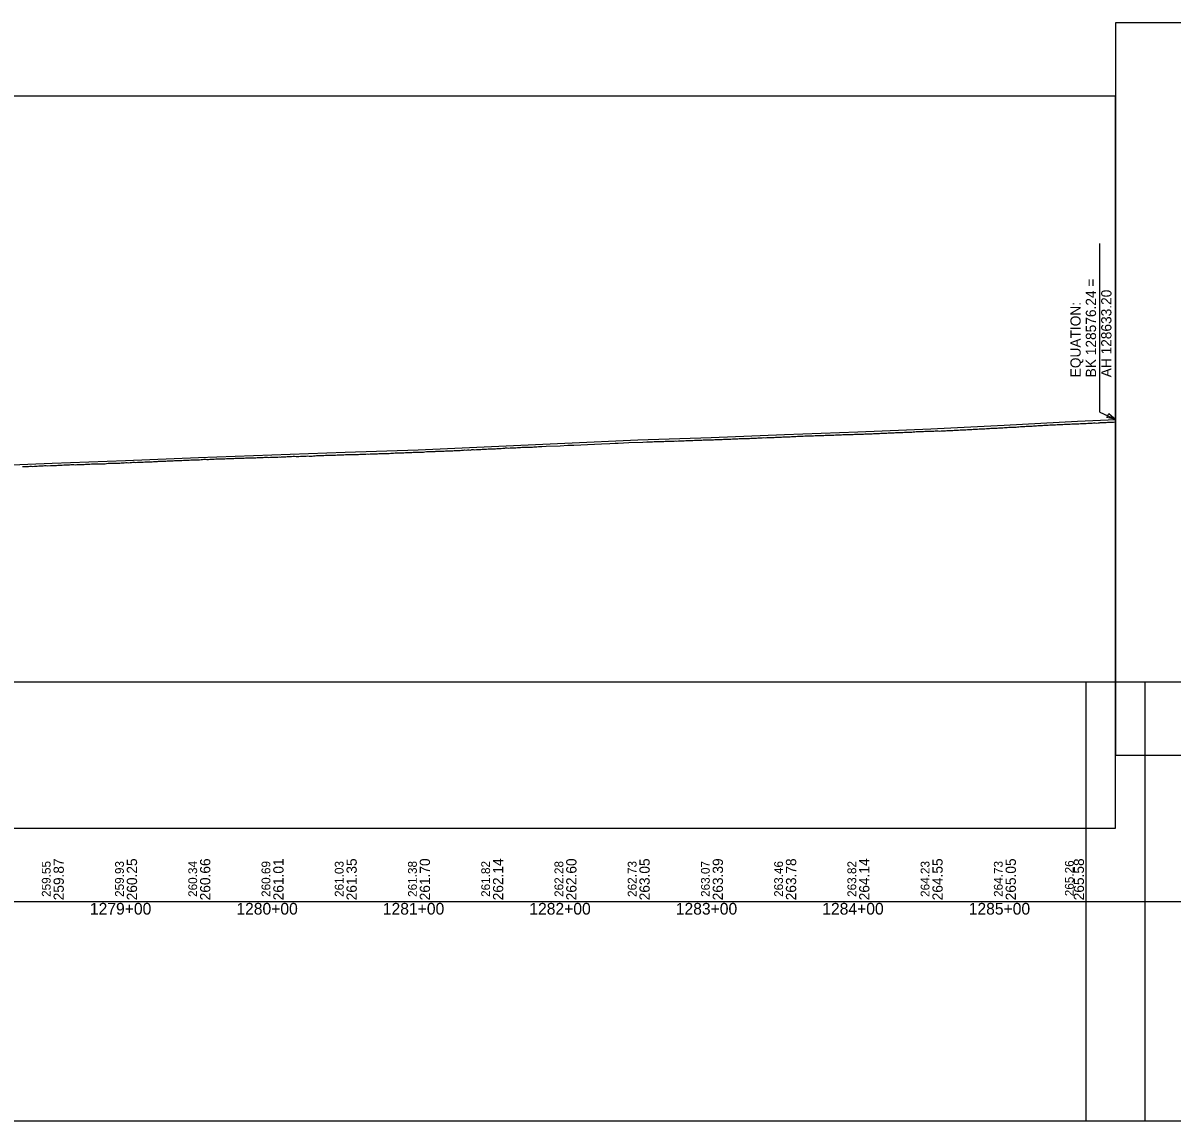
# Model space of a CAD drawing. Extents: x -3627 to 47473, y 2850 to 4350.
# Drawn here: x 15207 to 15992, y 2850 to 3600 of the extents above; entities that cross this region are included whole.
import ezdxf

# ---------------------------------------------------------------- set-up
doc = ezdxf.new("R2010")
doc.units = 0
for name, color, linetype in [('RD_DDB_Profile_EX', 7, 'Continuous'), ('RD_DDB_Profile_PR', 7, 'Continuous'), ('RD_DDB_StaTX', 7, 'Continuous'), ('RD_DDB_StripGrade', 7, 'Continuous'), ('RD_DDB_VCLbl', 7, 'Continuous'), ('RD_GPK_Profile_Cell', 7, 'Continuous'), ('RD_SHT_ShtClip', 7, 'Continuous')]:
    doc.layers.add(name, color=color, linetype=linetype)

msp = doc.modelspace()

# ---------------------------------------------------------------- linework, layer by layer
at = {"layer": 'RD_DDB_Profile_EX'}
for points in [[(15881.451196, 3323.85646), (15882.423116, 3323.95), (15883.423463, 3323.95), (15884.418069, 3323.956615), (15885.424679, 3324.013165), (15886.419282, 3324.15), (15887.41962, 3324.25), (15888.42183, 3324.3), (15889.420835, 3324.343355), (15890.4222, 3324.44327), (15891.424419, 3324.45), (15892.417994, 3324.5068), (15893.424781, 3324.556795), (15894.419207, 3324.6), (15895.420583, 3324.7), (15896.426294, 3324.6637), (15897.421796, 3324.83631), (15898.422092, 3324.89308), (15899.423454, 3324.92802), (15900.424384, 3324.97764), (15901.424671, 3325.07095), (15902.419335, 3325.156995), (15903.420494, 3325.15705), (15904.427249, 3325.228855), (15905.420825, 3325.321815), (15906.423081, 3325.314235), (15907.417768, 3325.364255), (15908.423403, 3325.46422), (15909.425667, 3325.564365), (15910.419243, 3325.60718), (15911.420616, 3325.607265), (15912.427126, 3325.614465), (15913.421829, 3325.657245), (15914.422061, 3325.792685), (15915.417694, 3325.80731), (15916.424416, 3325.76462), (15917.424638, 3325.85), (15918.420289, 3325.864755), (15919.420509, 3325.9149), (15920.420578, 3325.95737), (15921.421723, 3326.00743), (15922.423094, 3326.06503), (15923.416669, 3326.115025), (15924.424308, 3326.15), (15925.425678, 3326.15), (15926.419254, 3326.28485), (15927.421583, 3326.311775), (15928.420468, 3326.257555), (15929.421839, 3326.34236), (15930.422974, 3326.384605), (15931.423053, 3326.43476), (15932.423224, 3326.49231), (15933.425557, 3326.5), (15934.420343, 3326.55), (15935.425799, 3326.642245), (15936.421555, 3326.6345), (15937.421715, 3326.6), (15938.423083, 3326.792095), (15939.42293, 3326.7922), (15940.424298, 3326.757885), (15941.417873, 3326.876345), (15942.434896, 3326.94205), (15942.956564, 3327.015865), (15943.963958, 3327.05), (15944.965018, 3327.1), (15945.959348, 3327.06593), (15946.965961, 3327.157965), (15947.960289, 3327.292055), (15948.961338, 3327.308015), (15949.957103, 3327.35801), (15950.962282, 3327.392005), (15951.965544, 3327.44194), (15952.95909, 3327.5), (15953.566013, 3327.535008)], [(15681.807675, 3315.538865), (15682.808492, 3315.5723), (15683.807862, 3315.54427), (15684.807231, 3315.57197), (15685.808635, 3315.65), (15687.029535, 3315.71094), (15687.806753, 3315.721655), (15688.801588, 3315.77162), (15689.807375, 3315.82156), (15690.802205, 3315.771525), (15691.801493, 3315.882015), (15692.808516, 3315.95), (15693.399062, 3315.978805), (15694.397421, 3315.976455), (15695.39578, 3315.9271), (15696.440924, 3316.10253), (15697.389627, 3316.13972), (15698.393255, 3316.119305), (15699.391536, 3316.12027), (15700.386037, 3316.180345), (15701.384308, 3316.25), (15702.383517, 3316.280195), (15703.389081, 3316.29013), (15704.381768, 3316.3), (15705.380057, 3316.31235), (15706.378345, 3316.41321), (15707.377538, 3316.47141), (15708.208215, 3316.461655), (15709.208444, 3316.53095), (15710.207219, 3316.562215), (15711.208653, 3316.66254), (15712.202232, 3316.740635), (15713.209895, 3316.77804), (15714.208691, 3316.74634), (15715.208686, 3316.827515), (15716.203674, 3316.86837), (15717.203654, 3316.927265), (15718.210153, 3316.90909), (15719.208991, 3316.88694), (15720.205107, 3316.90996), (15721.203942, 3317.03215), (15722.20529, 3317.123475), (15723.210465, 3317.191175), (15724.20653, 3317.2), (15725.205387, 3317.19126), (15726.206704, 3317.224025), (15727.377624, 3317.29141), (15728.206837, 3317.37403), (15729.206823, 3317.382885), (15730.205722, 3317.408475), (15731.207007, 3317.416785), (15732.200586, 3317.45839), (15733.208249, 3317.508375), (15734.20717, 3317.50829), (15735.207371, 3317.6), (15736.202003, 3317.66641), (15737.202191, 3317.708135), (15738.208608, 3317.75), (15739.208803, 3317.808035), (15740.208794, 3317.857935), (15741.203592, 3317.9), (15742.203568, 3317.90785), (15743.209023, 3317.9235), (15744.209219, 3317.97329), (15745.203793, 3318.007745), (15746.203975, 3317.97302), (15747.203961, 3318.072725), (15748.210654, 3318.130285), (15749.205203, 3318.16511), (15750.145586, 3318.165095), (15751.139162, 3318.172635), (15752.1468, 3318.215055), (15753.140376, 3318.26505), (15754.148014, 3318.322525), (15755.14159, 3318.37252), (15756.149228, 3318.414975), (15757.142804, 3318.407485), (15758.143945, 3318.44246), (15759.144018, 3318.5), (15760.144215, 3318.507535), (15761.145232, 3318.557445), (15762.138808, 3318.607445), (15763.14112, 3318.61502), (15764.140022, 3318.642575), (15765.208411, 3318.7), (15766.207027, 3318.764885), (15767.209108, 3318.80752), (15768.208532, 3318.80745), (15769.210618, 3318.86506), (15770.20546, 3318.90754), (15771.211314, 3318.94245), (15772.20616, 3318.95756), (15773.212826, 3318.972675), (15774.207674, 3319.02271), (15775.209775, 3319.05765), (15776.208373, 3319.1), (15777.210471, 3319.11535), (15778.209888, 3319.1152), (15779.211991, 3319.115365), (15780.210586, 3319.165245), (15781.212686, 3319.17312)], [(15781.212686, 3319.17312), (15782.20756, 3319.265435), (15783.214209, 3319.31543), (15784.209085, 3319.373175), (15785.214902, 3319.35774), (15786.209782, 3319.39225), (15787.211898, 3319.465665), (15788.21131, 3319.515515), (15789.21343, 3319.59216), (15790.212006, 3319.59222), (15791.214123, 3319.6), (15792.213535, 3319.65779), (15793.215658, 3319.757875), (15794.209722, 3319.742095), (15795.21635, 3319.8), (15796.21126, 3319.85), (15797.217887, 3319.90791), (15798.2128, 3320.00792), (15799.206873, 3320.0159), (15800.213495, 3320.015895), (15801.208416, 3320.15), (15802.215037, 3320.15796), (15803.209961, 3320.2), (15804.215731, 3320.21597), (15805.210659, 3320.257995), (15806.212811, 3320.258085), (15807.212206, 3320.27402), (15808.213503, 3320.35811), (15809.212903, 3320.45), (15810.238378, 3320.508095), (15811.23332, 3320.46621), (15812.232744, 3320.508025), (15813.234001, 3320.56627), (15814.23343, 3320.608055), (15815.240042, 3320.708055), (15816.234978, 3320.791935), (15817.234393, 3320.857985), (15818.235663, 3320.866185), (15819.235084, 3320.858015), (15820.230015, 3320.95), (15821.23663, 3321), (15822.230708, 3321.05), (15823.249337, 3321.1), (15824.249442, 3321.134155), (15825.243807, 3321.1), (15826.249054, 3321.11577), (15827.243419, 3321.15), (15828.242131, 3321.19225), (15829.245217, 3321.292175), (15830.243122, 3321.34227), (15831.237469, 3321.39229), (15832.243565, 3321.357675), (15833.237908, 3321.28062), (15834.244557, 3321.434695), (15835.243277, 3321.43492), (15836.237606, 3321.45752), (15837.243738, 3321.507485), (15838.237289, 3321.6), (15839.237305, 3321.65), (15840.239054, 3321.607445), (15841.237771, 3321.657335), (15842.238753, 3321.70741), (15843.237489, 3321.8427), (15844.237479, 3321.85), (15845.239237, 3321.90726), (15846.23722, 3321.957165), (15847.231513, 3322.01429), (15848.237714, 3322.064225), (15849.233242, 3322.05711), (15850.238711, 3322.15), (15851.232998, 3322.207075), (15852.23173, 3322.25696), (15853.237966, 3322.26386), (15854.232725, 3322.30694), (15855.231457, 3322.370485), (15856.233233, 3322.45689), (15857.231973, 3322.50678), (15858.233036, 3322.6), (15859.23297, 3322.64324), (15860.227221, 3322.7), (15861.233494, 3322.75), (15862.227046, 3322.75), (15863.225794, 3322.8), (15864.23324, 3322.813155), (15865.227474, 3322.90656), (15866.22554, 3323), (15867.227332, 3323.086945), (15868.226088, 3323.137165), (15869.229007, 3323.14351), (15870.227087, 3323.16279), (15871.450204, 3323.206365), (15872.451677, 3323.256425), (15873.450273, 3323.4), (15874.452789, 3323.45), (15875.454257, 3323.45), (15876.448565, 3323.54355), (15877.454312, 3323.63713), (15878.456833, 3323.686985), (15879.451147, 3323.75), (15880.452612, 3323.84345), (15881.451196, 3323.85646)], [(15527.035923, 3309.085395), (15527.976104, 3309.157295), (15528.976679, 3309.16472), (15529.975146, 3309.214595), (15530.980417, 3309.3), (15531.974188, 3309.378115), (15532.979459, 3309.420895), (15533.972796, 3309.393615), (15534.978501, 3309.61455), (15535.971838, 3309.65727), (15536.447312, 3309.680885), (15536.977481, 3309.70727), (15537.9707, 3309.75), (15538.977085, 3309.671065), (15539.974215, 3309.757115), (15540.97589, 3309.90721), (15541.973023, 3309.91425), (15542.974696, 3309.87157), (15543.972611, 3309.87127), (15544.973501, 3309.935665), (15545.971404, 3309.971735), (15547.007704, 3309.98572), (15548.006044, 3310.18584), (15549.29227, 3310.192885), (15550.292937, 3310.157185), (15551.300722, 3310.30732), (15552.301773, 3310.35), (15553.297633, 3310.33487), (15554.2983, 3310.334735), (15555.298093, 3310.376855), (15556.29995, 3310.4), (15557.30052, 3310.447055), (15558.3072, 3310.56597), (15559.303008, 3310.616245), (15560.304933, 3310.64916), (15561.63813, 3310.7332), (15564.681479, 3310.86683), (15574.092868, 3311.279885), (15579.483723, 3311.516375), (15583.119319, 3311.680475), (15583.504257, 3311.697845), (15588.268414, 3311.91276), (15592.915645, 3312.1168), (15602.327034, 3312.52971), (15608.104929, 3312.78302), (15611.738423, 3312.946875), (15613.810919, 3313.040265), (15621.149812, 3313.361865), (15630.561201, 3313.77392), (15633.329516, 3313.896595), (15634.335706, 3313.95842), (15635.335492, 3313.996615), (15636.335916, 3313.996665), (15637.331402, 3313.996855), (15638.331183, 3314.08505), (15639.329655, 3314.120055), (15640.331354, 3314.16997), (15641.331035, 3314.22324), (15642.335825, 3314.161665), (15642.939698, 3314.135075), (15643.941113, 3314.15835), (15644.946378, 3314.20859), (15645.942133, 3314.28526), (15646.941392, 3314.323425), (15647.948807, 3314.3089), (15648.944568, 3314.309075), (15649.383979, 3314.33097), (15649.943709, 3314.3353), (15650.94522, 3314.42376), (15651.946462, 3314.46185), (15652.945511, 3314.5), (15653.939984, 3314.473685), (15654.948264, 3314.52375), (15655.947313, 3314.58547), (15656.941785, 3314.597485), (15657.947872, 3314.609415), (15658.945598, 3314.65963), (15659.944431, 3314.785585), (15660.816126, 3314.85), (15661.817677, 3314.86188), (15662.818542, 3314.92359), (15663.818065, 3314.80865), (15664.819625, 3314.873615), (15665.817201, 3314.961725), (15666.812396, 3315.014785), (15667.813245, 3315.046605), (15668.206757, 3315.046635), (15668.819093, 3315.04658), (15669.814192, 3315.058235), (15670.813628, 3315.107865), (15671.817539, 3315.17309), (15672.813933, 3315.18457), (15673.813377, 3315.23435), (15674.808453, 3315.322905), (15675.814301, 3315.322885), (15676.811864, 3315.334055), (15677.808198, 3315.37266), (15678.813981, 3315.37262), (15679.81335, 3315.42245), (15680.808314, 3315.46122), (15681.807675, 3315.538865)], [(15331.010899, 3301.95723), (15332.015857, 3301.988405), (15333.013696, 3301.91911), (15334.013103, 3301.92858), (15335.017602, 3301.988215), (15336.015441, 3302.128525), (15337.01374, 3302.147495), (15338.011577, 3302.17836), (15339.017624, 3302.21899), (15340.015361, 3302.22831), (15341.014645, 3302.22819), (15342.017971, 3302.26886), (15343.011, 3302.328365), (15344.010287, 3302.297075), (15344.349353, 3302.297005), (15345.353641, 3302.37825), (15346.35326, 3302.437505), (15347.350231, 3302.446685), (15348.354526, 3302.50611), (15349.354136, 3302.555795), (15350.352348, 3302.59615), (15351.358038, 3302.627755), (15352.355028, 3302.6776), (15353.354614, 3302.68659), (15354.353512, 3302.76847), (15355.351723, 3302.7775), (15356.351298, 3302.736455), (15357.630922, 3302.805055), (15358.353986, 3302.85), (15359.352192, 3302.891005), (15360.350399, 3302.941085), (15361.356085, 3302.935695), (15362.353116, 3302.91772), (15363.352647, 3302.958795), (15364.351548, 3303.008875), (15365.349754, 3303.05), (15366.349266, 3303.067455), (15367.352487, 3303.11747), (15368.351996, 3303.15866), (15369.350197, 3303.158565), (15370.355881, 3303.167125), (15371.354082, 3303.25), (15372.35117, 3303.324815), (15373.356854, 3303.32482), (15374.349534, 3303.325155), (15375.348979, 3303.316615), (15376.4537, 3303.33991), (15377.35053, 3303.458205), (15378.349955, 3303.51623), (15379.354426, 3303.524255), (15380.353833, 3303.523985), (15381.353214, 3303.51581), (15382.357711, 3303.565755), (15383.357074, 3303.538935), (15383.871849, 3303.63908), (15384.876042, 3303.715575), (15385.874354, 3303.63079), (15386.873814, 3303.66196), (15387.87114, 3303.780635), (15388.875225, 3303.78048), (15389.874681, 3303.873), (15390.872844, 3303.992435), (15391.876947, 3304.02742), (15392.86917, 3304.007495), (15393.874559, 3303.97989), (15394.870615, 3303.97949), (15395.276478, 3303.97961), (15395.870005, 3303.987065), (15396.867996, 3304.0865), (15397.872013, 3304.12175), (15398.864075, 3304.07884), (15399.869331, 3304.050215), (15400.866065, 3304.192285), (15401.866632, 3304.249685), (15402.86259, 3304.1989), (15403.866664, 3304.205495), (15404.867186, 3304.205885), (15405.863796, 3304.327395), (15406.867765, 3304.413575), (15407.860799, 3304.4635), (15408.864778, 3304.47007), (15409.860677, 3304.47627), (15410.861048, 3304.576425), (15411.857666, 3304.57588), (15412.862794, 3304.56927), (15414.099256, 3304.71217), (15414.858581, 3304.78153), (15415.856127, 3304.71851), (15417.858553, 3304.78065), (15418.856092, 3304.741955), (15419.855247, 3304.736075), (15420.851752, 3304.91173), (15421.856755, 3304.923225), (15422.848404, 3305.03449), (15423.851765, 3305.11706), (15424.849109, 3305.072155), (15425.848161, 3305.09438), (15426.55635, 3305.138285), (15427.555468, 3305.171915), (15428.554584, 3305.232925), (15429.554695, 3305.238545)], [(15429.554695, 3305.238545), (15430.553273, 3305.222105), (15431.552384, 3305.166605), (15432.560533, 3305.18378), (15432.922034, 3305.23809), (15433.559508, 3305.316895), (15434.558412, 3305.278145), (15435.558332, 3305.23945), (15436.509598, 3305.333905), (15437.508817, 3305.522675), (15438.512456, 3305.433675), (15439.511671, 3305.43941), (15440.511823, 3305.466975), (15441.511041, 3305.494325), (15442.51024, 3305.632925), (15443.509355, 3305.577205), (15444.50847, 3305.61141), (15445.507585, 3305.705715), (15446.507651, 3305.71719), (15447.506767, 3305.705735), (15448.505884, 3305.71149), (15449.505, 3305.717255), (15450.509161, 3305.85567), (15451.744811, 3305.9558), (15452.515617, 3305.923055), (15453.51463, 3305.86728), (15454.513643, 3305.917265), (15455.512656, 3305.873005), (15456.511669, 3305.90575), (15457.510026, 3305.99604), (15458.509995, 3306.078805), (15459.509008, 3306.16727), (15460.508021, 3306.223015), (15461.506998, 3306.317235), (15462.510961, 3306.344355), (15463.509873, 3306.35), (15464.509719, 3306.37249), (15465.508629, 3306.32804), (15466.507539, 3306.36678), (15467.506449, 3306.438845), (15468.505359, 3306.588875), (15469.511646, 3306.644375), (15470.567589, 3306.688765), (15471.510304, 3306.588815), (15471.843599, 3306.588895), (15472.843697, 3306.677235), (15473.842702, 3306.82734), (15474.848492, 3306.78857), (15475.841799, 3306.73845), (15476.848463, 3306.894165), (15477.841035, 3306.938185), (15478.846786, 3306.9), (15479.978978, 3306.86895), (15480.845844, 3306.906055), (15481.839175, 3307.093895), (15482.845819, 3307.23154), (15483.83917, 3307.237595), (15484.844863, 3307.19376), (15485.838224, 3307.281135), (15486.843903, 3307.33735), (15487.837273, 3307.35), (15488.843921, 3307.412845), (15489.390367, 3307.440315), (15489.84397, 3307.45), (15490.842941, 3307.49351), (15491.916091, 3307.46696), (15492.914544, 3307.547515), (15493.916205, 3307.636615), (15494.914658, 3307.636705), (15495.921693, 3307.65), (15496.914772, 3307.670195), (15497.921807, 3307.75), (15498.91487, 3307.836365), (15499.92177, 3307.82263), (15500.915452, 3307.836265), (15501.921613, 3307.87928), (15502.915302, 3307.986135), (15503.921457, 3307.97909), (15504.922529, 3308.0288), (15505.922055, 3308.050855), (15506.922369, 3308.12861), (15508.213145, 3308.30749), (15508.922885, 3308.357175), (15509.9203, 3308.30712), (15510.922461, 3308.392785), (15511.975007, 3308.39281), (15512.981751, 3308.26441), (15513.975318, 3308.578345), (15514.981268, 3308.607245), (15515.97484, 3308.549175), (15516.980785, 3308.61982), (15517.97432, 3308.7146), (15518.980945, 3308.657305), (15519.978297, 3308.735525), (15520.978986, 3308.828065), (15521.977576, 3308.835485), (15522.978264, 3308.814665), (15523.977655, 3308.871795), (15524.977542, 3309.042645), (15525.976936, 3309.1), (15527.035923, 3309.085395)], [(15207.048699, 3297.002285), (15207.912279, 3297.121585), (15208.917315, 3297.160795), (15209.917083, 3297.117305), (15211.232967, 3297.154475), (15212.236724, 3297.22184), (15213.230763, 3297.18907), (15214.234519, 3297.15), (15215.23827, 3297.282935), (15216.460088, 3297.30563), (15217.235989, 3297.361005), (15218.233164, 3297.45), (15219.23175, 3297.510995), (15220.235383, 3297.5), (15221.232566, 3297.578095), (15222.237471, 3297.65), (15223.230141, 3297.704815), (15224.454351, 3297.626825), (15226.231318, 3297.83295), (15227.23484, 3297.78296), (15228.233154, 3297.68715), (15229.236687, 3297.69806), (15230.235162, 3297.82654), (15231.232218, 3297.915185), (15232.235754, 3297.915195), (15233.229547, 3297.95426), (15234.233085, 3298.043415)], [(15234.233085, 3298.043415), (15235.282866, 3298.19736), (15236.230301, 3298.15), (15237.233726, 3298.1), (15238.23065, 3298.264425), (15239.235318, 3298.303525), (15240.227721, 3298.332105), (15241.231159, 3298.382075), (15242.23406, 3298.331915), (15243.226451, 3298.281905), (15244.229899, 3298.331875), (15244.694255, 3298.3783), (15245.22796, 3298.431535), (15246.226775, 3298.513425), (15247.230114, 3298.46329), (15248.228102, 3298.502145), (15249.169572, 3298.42283), (15250.163217, 3298.591465), (15251.166712, 3298.63103), (15252.171522, 3298.680895), (15253.162239, 3298.73079), (15254.167047, 3298.801085), (15255.164345, 3298.790425), (15256.551842, 3298.8005), (15257.549132, 3298.80064), (15258.553026, 3298.940285), (15259.552175, 3298.97024), (15260.552287, 3298.900725), (15261.555218, 3298.95055), (15262.55533, 3298.990545), (15263.552602, 3298.971145), (15264.552488, 3299.061065), (15265.555191, 3299.23039), (15266.55411, 3299.240665), (15267.553995, 3299.27036), (15268.556699, 3299.320265), (15269.554717, 3299.280385), (15270.553632, 3299.33049), (15271.553516, 3299.38053), (15272.556224, 3299.36078), (15272.928422, 3299.360855), (15273.555963, 3299.36082), (15274.552791, 3299.460845), (15275.552446, 3299.500715), (15276.554936, 3299.60042), (15277.553624, 3299.68032), (15278.553277, 3299.69044), (15279.55577, 3299.660305), (15280.553573, 3299.680275), (15281.552259, 3299.79023), (15282.551859, 3299.930175), (15283.55414, 3299.93995), (15284.546199, 3299.86932), (15285.544666, 3299.90949), (15286.545142, 3299.95895), (15287.544544, 3300.0589), (15288.543009, 3300.068795), (15289.54241, 3300.108915), (15290.544706, 3300.168235), (15291.7512, 3300.19871), (15292.540603, 3300.188895), (15293.539772, 3300.22911), (15294.541864, 3300.30772), (15295.540106, 3300.35772), (15296.539265, 3300.398), (15297.539625, 3300.438), (15298.538777, 3300.52844), (15299.347763, 3300.56896), (15299.996046, 3300.597405), (15301.162589, 3300.632845), (15302.000162, 3300.630945), (15302.99945, 3300.671515), (15304.002627, 3300.65724), (15305.000788, 3300.666695), (15306.000082, 3300.918995), (15306.998242, 3300.928455), (15308.004092, 3300.928585), (15309.002253, 3300.97855), (15310.000008, 3300.987875), (15311.004682, 3301.078575), (15311.999072, 3301.088255), (15312.997146, 3301.1477), (15313.996352, 3301.218995), (15314.999441, 3301.21906), (15315.99752, 3301.24754), (15317.012036, 3301.27853), (15318.016736, 3301.288235), (15319.014779, 3301.34768), (15320.014386, 3301.43812), (15321.012324, 3301.42849), (15322.017384, 3301.53828), (15323.015326, 3301.54768), (15324.013267, 3301.638005), (15325.019432, 3301.647785), (15326.017373, 3301.716655), (15327.015774, 3301.71667), (15328.009018, 3301.69785), (15329.015192, 3301.788505), (15329.396755, 3301.826685), (15330.013065, 3301.89792), (15331.010899, 3301.95723)]]:
    msp.add_lwpolyline(points, dxfattribs=at)
at = {"layer": 'RD_DDB_Profile_PR'}
for p, q in [((15942.57, 3334.101528), (15942.57, 3449.301528)), ((15942.57, 3334.101529), (15953.57, 3329.178823))]:
    msp.add_line(p, q, dxfattribs=at)
msp.add_lwpolyline([(15177.33, 3297.2595), (15227.33, 3299.374), (15277.33, 3301.2625), (15327.33, 3303.3105), (15377.33, 3305.0555), (15427.33, 3306.7645), (15477.33, 3308.5155), (15527.33, 3310.708), (15577.33, 3313.022), (15627.33, 3315.2325), (15677.33, 3316.954), (15727.33, 3318.8885), (15777.33, 3320.7155), (15827.33, 3322.7535), (15877.33, 3325.2255), (15927.33, 3327.9095), (15953.57, 3329.178823)], dxfattribs=at)
msp.add_lwpolyline([(15948.853596, 3333.179515), (15953.57, 3329.178823), (15947.525789, 3330.489361)], close=True, dxfattribs=at)
at = {"layer": 'RD_DDB_VCLbl'}
msp.add_line((15953.566013, 3327.535008), (15953.566013, 3327.535008), dxfattribs=at)
at = {"layer": 'RD_GPK_Profile_Cell'}
msp.add_line((1000, 3000), (46705.077602, 3000), dxfattribs=at)
at = {"layer": 'RD_SHT_ShtClip'}
for points in [[(15953.33, 3600), (15953.33, 3100), (17453.33, 3100), (17453.33, 3100), (17453.33, 3600), (17453.33, 3600)], [(14500.33, 3550), (14500.33, 3050), (15953.33, 3050), (15953.33, 3050), (15953.33, 3550), (15953.33, 3550)], [(14480.33, 3150), (15973.33, 3150), (15973.33, 2850), (14480.33, 2850)], [(15933.33, 3150), (17473.33, 3150), (17473.33, 2850), (15933.33, 2850)]]:
    msp.add_lwpolyline(points, close=True, dxfattribs=at)

# ---------------------------------------------------------------- texts
at = {"layer": 'RD_DDB_Profile_PR'}
for s, p in [('BK 128576.24 =', (15940.07, 3357.978823)), ('AH 128633.20', (15950.57, 3357.978823)), ('EQUATION:', (15929.57, 3357.978823))]:
    msp.add_text(s, height=7, rotation=90, dxfattribs=at).set_placement(p)
at = {"layer": 'RD_DDB_StaTX'}
for s, p in [('1279+00', (15253.125471, 2991)), ('1280+00', (15353.125471, 2991)), ('1281+00', (15453.125471, 2991)), ('1282+00', (15553.125471, 2991)), ('1283+00', (15653.125471, 2991)), ('1284+00', (15753.125471, 2991)), ('1285+00', (15853.125471, 2991))]:
    msp.add_text(s, height=8, dxfattribs=at).set_placement(p)
at = {"layer": 'RD_DDB_StripGrade'}
for s, height, p in [('259.87', 7, (15235.33, 3000.75)), ('260.25', 7, (15285.33, 3000.75)), ('260.66', 7, (15335.33, 3000.75)), ('261.01', 7, (15385.33, 3000.75)), ('261.35', 7, (15435.33, 3000.75)), ('261.70', 7, (15485.33, 3000.75)), ('262.14', 7, (15535.33, 3000.75)), ('262.60', 7, (15585.33, 3000.75)), ('263.05', 7, (15635.33, 3000.75)), ('263.39', 7, (15685.33, 3000.75)), ('263.78', 7, (15735.33, 3000.75)), ('264.14', 7, (15785.33, 3000.75)), ('264.55', 7, (15835.33, 3000.75)), ('265.05', 7, (15885.33, 3000.75)), ('265.58', 7, (15931.83, 3000.75)), ('259.55', 6, (15226.33, 3003.073688)), ('259.93', 6, (15276.33, 3003.073688)), ('260.34', 6, (15326.33, 3003.073688)), ('260.69', 6, (15376.33, 3003.073688)), ('261.03', 6, (15426.33, 3003.073688)), ('261.38', 6, (15476.33, 3003.073688)), ('261.82', 6, (15526.33, 3003.073688)), ('262.28', 6, (15576.33, 3003.073688)), ('262.73', 6, (15626.33, 3003.073688)), ('263.07', 6, (15676.33, 3003.073688)), ('263.46', 6, (15726.33, 3003.073688)), ('263.82', 6, (15776.33, 3003.073688)), ('264.23', 6, (15826.33, 3003.073688)), ('264.73', 6, (15876.33, 3003.073688)), ('265.26', 6, (15924.83, 3003.530067))]:
    msp.add_text(s, height=height, rotation=90, dxfattribs=at).set_placement(p)

doc.saveas('drawing.dxf')
